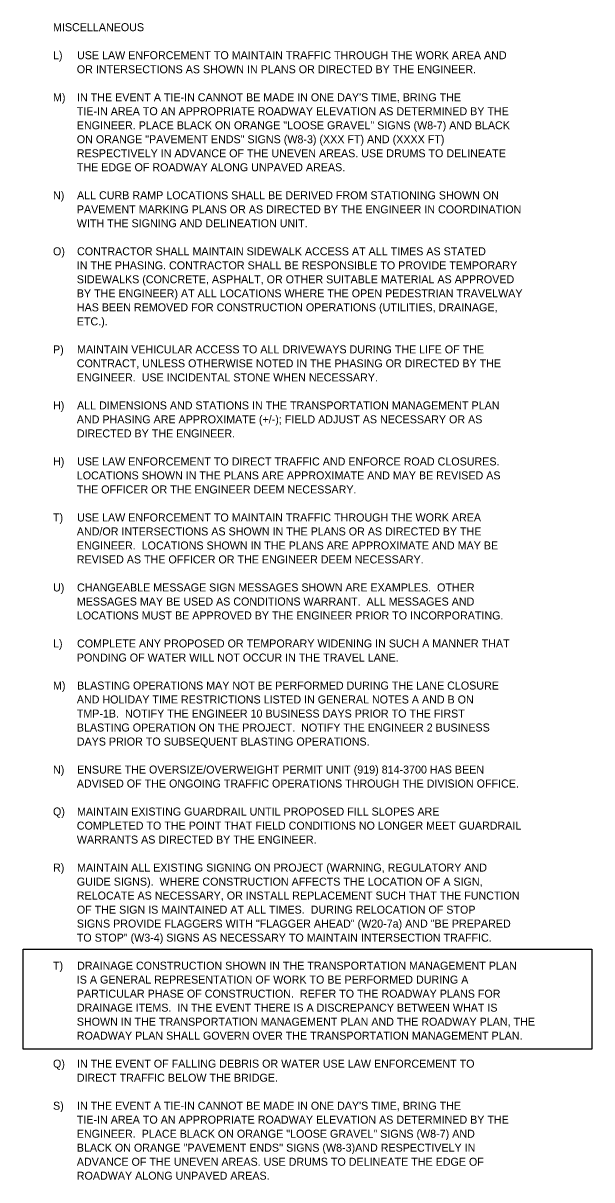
# Model space of a CAD drawing. Extents: x 2485109 to 2490507, y 368607 to 371384.
# Drawn here: x 2488602 to 2489099, y 368607 to 369618 of the extents above; entities that cross this region are included whole.
import ezdxf

# ---------------------------------------------------------------- set-up
doc = ezdxf.new("R2010")
doc.units = 0
doc.layers.add('Scratch_Level_2', color=7, linetype='Continuous')
doc.layers.add('TC SHEET TEXT', color=7, linetype='Continuous')

msp = doc.modelspace()

# ---------------------------------------------------------------- linework, layer by layer
at = {"layer": 'Scratch_Level_2'}
msp.add_lwpolyline([(2488602.1, 368808.4), (2489099.2, 368808.4), (2489099.2, 368720.8), (2488602.1, 368720.8)], close=True, dxfattribs=at)

# ---------------------------------------------------------------- texts
at = {"layer": 'TC SHEET TEXT'}
for s, p in [('MISCELLANEOUS', (2488628.2, 369611.2)), ('L)', (2488628.2, 369586.7)), ('USE LAW ENFORCEMENT TO MAINTAIN TRAFFIC THROUGH THE WORK AREA AND', (2488649.2, 369586.7)), ('        OR INTERSECTIONS AS SHOWN IN PLANS OR DIRECTED BY THE ENGINEER.', (2488628.2, 369574.4)), ('M)', (2488628.2, 369549.9)), ("IN THE EVENT A TIE-IN CANNOT BE MADE IN ONE DAY'S TIME, BRING THE", (2488649.2, 369549.9)), ('        TIE-IN AREA TO AN APPROPRIATE ROADWAY ELEVATION AS DETERMINED BY THE', (2488628.2, 369537.7)), ('        ENGINEER. PLACE BLACK ON ORANGE "LOOSE GRAVEL" SIGNS (W8-7) AND BLACK', (2488628.2, 369525.4)), ('        ON ORANGE "PAVEMENT ENDS" SIGNS (W8-3) (XXX FT) AND (XXXX FT)', (2488628.2, 369513.2)), ('        RESPECTIVELY IN ADVANCE OF THE UNEVEN AREAS. USE DRUMS TO DELINEATE', (2488628.2, 369500.9)), ('        THE EDGE OF ROADWAY ALONG UNPAVED AREAS.', (2488628.2, 369488.7)), ('N)', (2488628.2, 369464.2)), ('ALL CURB RAMP LOCATIONS SHALL BE DERIVED FROM STATIONING SHOWN ON', (2488649.2, 369464.2)), ('        PAVEMENT MARKING PLANS OR AS DIRECTED BY THE ENGINEER IN COORDINATION', (2488628.2, 369451.9)), ('        WITH THE SIGNING AND DELINEATION UNIT.', (2488628.2, 369439.7)), ('O)', (2488628.2, 369415.2)), ('CONTRACTOR SHALL MAINTAIN SIDEWALK ACCESS AT ALL TIMES AS STATED', (2488649.2, 369415.2)), ('        IN THE PHASING. CONTRACTOR SHALL BE RESPONSIBLE TO PROVIDE TEMPORARY', (2488628.2, 369402.9)), ('        SIDEWALKS (CONCRETE, ASPHALT, OR OTHER SUITABLE MATERIAL AS APPROVED', (2488628.2, 369390.7)), ('        BY THE ENGINEER) AT ALL LOCATIONS WHERE THE OPEN PEDESTRIAN TRAVELWAY', (2488628.2, 369378.4)), ('        HAS BEEN REMOVED FOR CONSTRUCTION OPERATIONS (UTILITIES, DRAINAGE,', (2488628.2, 369366.2)), ('        ETC.).', (2488628.2, 369353.9)), ('P)', (2488628.2, 369329.4)), ('MAINTAIN VEHICULAR ACCESS TO ALL DRIVEWAYS DURING THE LIFE OF THE', (2488649.2, 369329.4)), ('        CONTRACT, UNLESS OTHERWISE NOTED IN THE PHASING OR DIRECTED BY THE', (2488628.2, 369317.2)), ('        ENGINEER.  USE INCIDENTAL STONE WHEN NECESSARY.', (2488628.2, 369304.9)), ('H)', (2488628.2, 369280.4)), ('ALL DIMENSIONS AND STATIONS IN THE TRANSPORTATION MANAGEMENT PLAN', (2488649.2, 369280.4)), ('        AND PHASING ARE APPROXIMATE (+/-); FIELD ADJUST AS NECESSARY OR AS', (2488628.2, 369268.2)), ('        DIRECTED BY THE ENGINEER.', (2488628.2, 369255.9)), ('H)', (2488628.2, 369231.4)), ('USE LAW ENFORCEMENT TO DIRECT TRAFFIC AND ENFORCE ROAD CLOSURES.', (2488649.2, 369231.4)), ('        LOCATIONS SHOWN IN THE PLANS ARE APPROXIMATE AND MAY BE REVISED AS', (2488628.2, 369219.2)), ('        THE OFFICER OR THE ENGINEER DEEM NECESSARY.', (2488628.2, 369206.9)), ('T)', (2488628.2, 369182.4)), ('USE LAW ENFORCEMENT TO MAINTAIN TRAFFIC THROUGH THE WORK AREA', (2488649.2, 369182.4)), ('        AND/OR INTERSECTIONS AS SHOWN IN THE PLANS OR AS DIRECTED BY THE', (2488628.2, 369170.2)), ('        ENGINEER.  LOCATIONS SHOWN IN THE PLANS ARE APPROXIMATE AND MAY BE', (2488628.2, 369157.9)), ('        REVISED AS THE OFFICER OR THE ENGINEER DEEM NECESSARY.', (2488628.2, 369145.7)), ('U)', (2488628.2, 369121.2)), ('CHANGEABLE MESSAGE SIGN MESSAGES SHOWN ARE EXAMPLES.  OTHER', (2488649.2, 369121.2)), ('        MESSAGES MAY BE USED AS CONDITIONS WARRANT.  ALL MESSAGES AND', (2488628.2, 369108.9)), ('        LOCATIONS MUST BE APPROVED BY THE ENGINEER PRIOR TO INCORPORATING.', (2488628.2, 369096.7)), ('L)', (2488628.2, 369072.2)), ('COMPLETE ANY PROPOSED OR TEMPORARY WIDENING IN SUCH A MANNER THAT', (2488649.2, 369072.2)), ('        PONDING OF WATER WILL NOT OCCUR IN THE TRAVEL LANE.', (2488628.2, 369059.9)), ('M)', (2488628.2, 369035.4)), ('BLASTING OPERATIONS MAY NOT BE PERFORMED DURING THE LANE CLOSURE', (2488649.2, 369035.4)), ('        AND HOLIDAY TIME RESTRICTIONS LISTED IN GENERAL NOTES A AND B ON', (2488628.2, 369023.2)), ('        TMP-1B.  NOTIFY THE ENGINEER 10 BUSINESS DAYS PRIOR TO THE FIRST', (2488628.2, 369010.9)), ('        BLASTING OPERATION ON THE PROJECT.  NOTIFY THE ENGINEER 2 BUSINESS', (2488628.2, 368998.7)), ('        DAYS PRIOR TO SUBSEQUENT BLASTING OPERATIONS.', (2488628.2, 368986.4)), ('N)', (2488628.2, 368961.9)), ('ENSURE THE OVERSIZE/OVERWEIGHT PERMIT UNIT (919) 814-3700 HAS BEEN', (2488649.2, 368961.9)), ('        ADVISED OF THE ONGOING TRAFFIC OPERATIONS THROUGH THE DIVISION OFFICE.', (2488628.2, 368949.7)), ('Q)', (2488628.2, 368925.2)), ('MAINTAIN EXISTING GUARDRAIL UNTIL PROPOSED FILL SLOPES ARE', (2488649.2, 368925.2)), ('        COMPLETED TO THE POINT THAT FIELD CONDITIONS NO LONGER MEET GUARDRAIL', (2488628.2, 368912.9)), ('        WARRANTS AS DIRECTED BY THE ENGINEER.', (2488628.2, 368900.7)), ('R)', (2488628.2, 368876.2)), ('MAINTAIN ALL EXISTING SIGNING ON PROJECT (WARNING, REGULATORY AND', (2488649.2, 368876.2)), ('        GUIDE SIGNS).  WHERE CONSTRUCTION AFFECTS THE LOCATION OF A SIGN,', (2488628.2, 368863.9)), ('        RELOCATE AS NECESSARY, OR INSTALL REPLACEMENT SUCH THAT THE FUNCTION', (2488628.2, 368851.7)), ('        OF THE SIGN IS MAINTAINED AT ALL TIMES.  DURING RELOCATION OF STOP', (2488628.2, 368839.4)), ('        SIGNS PROVIDE FLAGGERS WITH "FLAGGER AHEAD" (W20-7a) AND "BE PREPARED', (2488628.2, 368827.2)), ('        TO STOP" (W3-4) SIGNS AS NECESSARY TO MAINTAIN INTERSECTION TRAFFIC.', (2488628.2, 368814.9)), ('T)', (2488628.2, 368790.4)), ('DRAINAGE CONSTRUCTION SHOWN IN THE TRANSPORTATION MANAGEMENT PLAN', (2488649.2, 368790.4)), ('        IS A GENERAL REPRESENTATION OF WORK TO BE PERFORMED DURING A', (2488628.2, 368778.2)), ('        PARTICULAR PHASE OF CONSTRUCTION.  REFER TO THE ROADWAY PLANS FOR', (2488628.2, 368765.9)), ('        DRAINAGE ITEMS.  IN THE EVENT THERE IS A DISCREPANCY BETWEEN WHAT IS', (2488628.2, 368753.7)), ('        SHOWN IN THE TRANSPORTATION MANAGEMENT PLAN AND THE ROADWAY PLAN, THE', (2488628.2, 368741.4)), ('        ROADWAY PLAN SHALL GOVERN OVER THE TRANSPORTATION MANAGEMENT PLAN.', (2488628.2, 368729.2)), ('Q)', (2488628.2, 368704.7)), ('IN THE EVENT OF FALLING DEBRIS OR WATER USE LAW ENFORCEMENT TO', (2488649.2, 368704.7)), ('        DIRECT TRAFFIC BELOW THE BRIDGE.', (2488628.2, 368692.4)), ('S)', (2488628.2, 368667.9)), ("IN THE EVENT A TIE-IN CANNOT BE MADE IN ONE DAY'S TIME, BRING THE", (2488649.2, 368667.9)), ('        TIE-IN AREA TO AN APPROPRIATE ROADWAY ELEVATION AS DETERMINED BY THE', (2488628.2, 368655.7)), ('        ENGINEER.  PLACE BLACK ON ORANGE "LOOSE GRAVEL" SIGNS (W8-7) AND', (2488628.2, 368643.4)), ("        BLACK ON ORANGE ''PAVEMENT ENDS'' SIGNS (W8-3)AND RESPECTIVELY IN", (2488628.2, 368631.2)), ('        ADVANCE OF THE UNEVEN AREAS. USE DRUMS TO DELINEATE THE EDGE OF', (2488628.2, 368618.9)), ('        ROADWAY ALONG UNPAVED AREAS.', (2488628.2, 368606.7))]:
    msp.add_text(s, height=7, dxfattribs=at).set_placement(p)

doc.saveas('drawing.dxf')
